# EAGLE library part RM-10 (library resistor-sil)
Divider 6 Murata M-Type
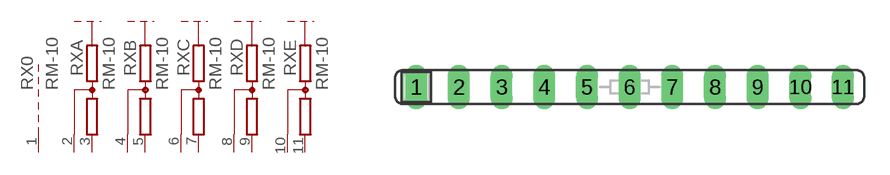
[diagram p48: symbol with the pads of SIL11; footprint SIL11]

Designator prefix RX; gates 0=R-P A=SIL-M B=SIL-M C=SIL-M D=SIL-M E=SIL-M

## RM-10 (OC_FARNELL: unknown; OC_NEWARK: unknown)  [SIL11]
1  0:2  pas
2  A:M1  pas
3  A:M2  pas
4  B:M1  pas
5  B:M2  pas
6  C:M1  pas
7  C:M2  pas
8  D:M1  pas
9  D:M2  pas
10  E:M1  pas
11  E:M2  pas

## Footprint SIL11 (pad centres in mm)
Single In Line
drill 0.813 long: 1 -12.7,0; 2 -10.16,0; 3 -7.62,0; 4 -5.08,0; 5 -2.54,0; 6 0,0; 7 2.54,0; 8 5.08,0; 9 7.62,0; 10 10.16,0; 11 12.7,0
